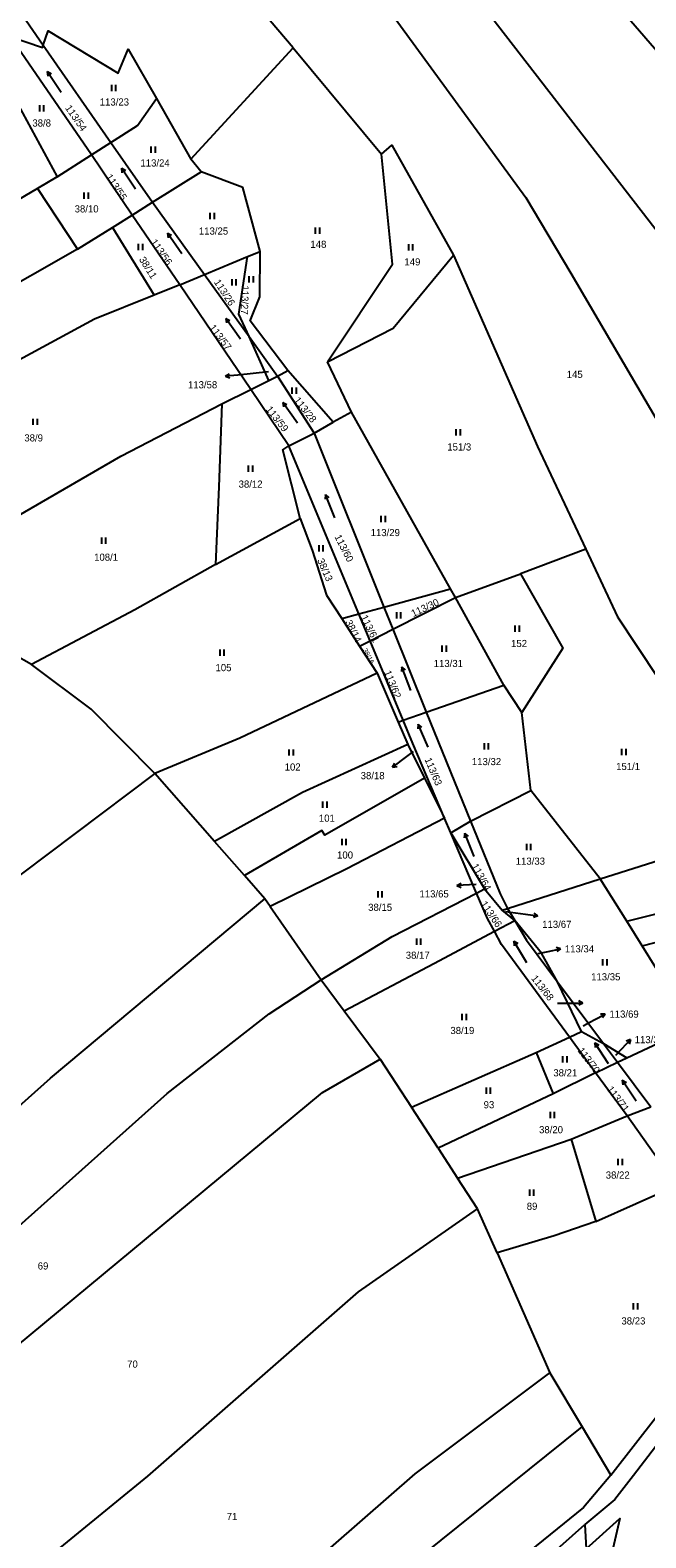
# Model space of a CAD drawing. Extents: x -7483133 to -743169, y -11317770 to -1127091.
# Drawn here: x -747508.3 to -747362, y -1131370.8 to -1131012.2 of the extents above; entities that cross this region are included whole.
import ezdxf

# ---------------------------------------------------------------- set-up
doc = ezdxf.new("R2010")
doc.units = 0
for name, color, linetype in [('Hranice parcel', 7, 'Continuous'), ('Parcelní čísla', 7, 'Continuous'), ('Pop  PČ popisy', 7, 'Continuous'), ('Značky kultur', 7, 'Continuous')]:
    doc.layers.add(name, color=color, linetype=linetype)

msp = doc.modelspace()

# ---------------------------------------------------------------- linework, layer by layer
at = {"layer": 'Hranice parcel'}
for p, q in [((-747445.77, -1131016.39), (-747480.85, -1130975.08)), ((-747511.77, -1131006.31), (-747505.21, -1131015.73)), ((-747493.76, -1131041.86), (-747513.08, -1131013.69)), ((-747505.21, -1131015.73), (-747489.11, -1131038.86)), ((-747470.12, -1131042.87), (-747445.77, -1131016.39)), ((-747445.77, -1131016.39), (-747424.82, -1131041.7)), ((-747478.31, -1131028.41), (-747470.12, -1131042.87)), ((-747493.76, -1131041.86), (-747489.11, -1131038.86)), ((-747489.11, -1131038.86), (-747479.21, -1131053.09)), ((-747501.87, -1131047.09), (-747493.76, -1131041.86)), ((-747484.08, -1131056.18), (-747493.76, -1131041.86)), ((-747467.67, -1131045.88), (-747470.12, -1131042.87)), ((-747501.87, -1131047.09), (-747506.57, -1131049.83)), ((-747479.21, -1131053.09), (-747467.67, -1131045.88)), ((-747506.57, -1131049.83), (-747497.04, -1131064.23)), ((-747484.08, -1131056.18), (-747479.21, -1131053.09)), ((-747479.21, -1131053.09), (-747466.89, -1131070.28)), ((-747497.04, -1131064.23), (-747488.78, -1131059.1)), ((-747488.78, -1131059.1), (-747484.08, -1131056.18)), ((-747488.78, -1131059.1), (-747478.83, -1131075.18)), ((-747472.77, -1131072.73), (-747484.08, -1131056.18)), ((-747466.89, -1131070.28), (-747456.65, -1131066.03)), ((-747456.65, -1131066.03), (-747453.62, -1131064.84)), ((-747472.77, -1131072.73), (-747478.83, -1131075.18)), ((-747472.77, -1131072.73), (-747466.89, -1131070.28)), ((-747455.83, -1131097.63), (-747472.77, -1131072.73)), ((-747466.89, -1131070.28), (-747456.29, -1131085.07)), ((-747456.29, -1131085.07), (-747449.55, -1131094.47)), ((-747451.56, -1131095.48), (-747456.29, -1131085.07)), ((-747431.95, -1131103.02), (-747437.65, -1131091.07)), ((-747451.56, -1131095.48), (-747449.55, -1131094.47)), ((-747449.55, -1131094.47), (-747447.06, -1131093.1)), ((-747449.55, -1131094.47), (-747440.84, -1131108.03)), ((-747436.27, -1131105.41), (-747447.06, -1131093.1)), ((-747462.74, -1131101.03), (-747455.83, -1131097.63)), ((-747455.83, -1131097.63), (-747451.56, -1131095.48)), ((-747446.81, -1131111.05), (-747455.83, -1131097.63)), ((-747440.84, -1131108.03), (-747436.27, -1131105.41)), ((-747431.95, -1131103.02), (-747436.27, -1131105.41)), ((-747408.38, -1131145.07), (-747431.95, -1131103.02)), ((-747446.81, -1131111.05), (-747440.84, -1131108.03)), ((-747440.84, -1131108.03), (-747424.22, -1131149.41)), ((-747430.18, -1131151.04), (-747446.81, -1131111.05)), ((-747464.26, -1131139.24), (-747444.14, -1131128.36)), ((-747376.22, -1131135.6), (-747391.74, -1131141.48)), ((-747407.22, -1131147.14), (-747391.74, -1131141.48)), ((-747424.22, -1131149.41), (-747408.38, -1131145.07)), ((-747407.22, -1131147.14), (-747408.38, -1131145.07)), ((-747422.11, -1131154.66), (-747407.22, -1131147.14)), ((-747395.7, -1131168), (-747407.22, -1131147.14)), ((-747434.26, -1131152.16), (-747430.18, -1131151.04)), ((-747434.26, -1131152.16), (-747430.03, -1131158.67)), ((-747430.18, -1131151.04), (-747424.22, -1131149.41)), ((-747427.53, -1131157.41), (-747430.18, -1131151.04)), ((-747424.22, -1131149.41), (-747422.11, -1131154.66)), ((-747427.53, -1131157.41), (-747422.11, -1131154.66)), ((-747422.11, -1131154.66), (-747414.16, -1131174.44)), ((-747508, -1131163.09), (-747518.15, -1131157.34)), ((-747430.03, -1131158.67), (-747427.53, -1131157.41)), ((-747430.03, -1131158.67), (-747425.84, -1131165.11)), ((-747419.66, -1131176.34), (-747427.53, -1131157.41)), ((-747425.84, -1131165.11), (-747420.83, -1131176.75)), ((-747414.16, -1131174.44), (-747395.7, -1131168)), ((-747391.42, -1131174.47), (-747395.7, -1131168)), ((-747420.83, -1131176.75), (-747419.66, -1131176.34)), ((-747420.83, -1131176.75), (-747418.53, -1131182.09)), ((-747419.66, -1131176.34), (-747414.16, -1131174.44)), ((-747414.16, -1131174.44), (-747403.63, -1131200.37)), ((-747389.33, -1131193.02), (-747391.42, -1131174.47)), ((-747418.53, -1131182.09), (-747414.55, -1131190.08)), ((-747464.5, -1131205.17), (-747478.68, -1131189)), ((-747414.55, -1131190.08), (-747409.79, -1131199.63)), ((-747403.63, -1131200.37), (-747389.33, -1131193.02)), ((-747372.79, -1131214.07), (-747389.33, -1131193.02)), ((-747408.32, -1131203.08), (-747409.79, -1131199.63)), ((-747408.32, -1131203.08), (-747403.63, -1131200.37)), ((-747372.79, -1131214.07), (-747335.3, -1131202.07)), ((-747457.41, -1131213.25), (-747464.5, -1131205.17)), ((-747402.18, -1131217.46), (-747408.32, -1131203.08)), ((-747408.32, -1131203.08), (-747400.3, -1131216.43)), ((-747452.5, -1131218.84), (-747457.41, -1131213.25)), ((-747402.18, -1131217.46), (-747400.3, -1131216.43)), ((-747400.3, -1131216.43), (-747396.13, -1131221.54)), ((-747394.81, -1131221.1), (-747372.79, -1131214.07)), ((-747366.49, -1131224.14), (-747372.79, -1131214.07)), ((-747451.24, -1131220.66), (-747452.5, -1131218.84)), ((-747451.24, -1131220.66), (-747439.12, -1131238.12)), ((-747397.95, -1131226.54), (-747393.08, -1131223.94)), ((-747396.13, -1131221.54), (-747394.81, -1131221.1)), ((-747393.08, -1131223.94), (-747396.13, -1131221.54)), ((-747394.81, -1131221.1), (-747393.08, -1131223.94)), ((-747362.83, -1131229.98), (-747366.49, -1131224.14)), ((-747359.55, -1131235.22), (-747362.83, -1131229.98)), ((-747439.12, -1131238.12), (-747433.68, -1131245.43)), ((-747377.23, -1131250.36), (-747382.92, -1131238.52)), ((-747382.92, -1131238.52), (-747372.02, -1131253.19)), ((-747433.68, -1131245.43), (-747425.11, -1131256.95)), ((-747366.48, -1131256.66), (-747350.79, -1131249.21)), ((-747388.07, -1131255.34), (-747380.11, -1131251.72)), ((-747380.11, -1131251.72), (-747377.23, -1131250.36)), ((-747373.91, -1131260.21), (-747380.11, -1131251.72)), ((-747377.23, -1131250.36), (-747372.02, -1131253.19)), ((-747417.7, -1131268.35), (-747388.07, -1131255.34)), ((-747388.07, -1131255.34), (-747384.01, -1131265.18)), ((-747372.02, -1131253.19), (-747366.48, -1131256.66)), ((-747372.02, -1131253.19), (-747368.67, -1131257.7)), ((-747368.67, -1131257.7), (-747366.48, -1131256.66)), ((-747425.11, -1131256.95), (-747417.7, -1131268.35)), ((-747373.91, -1131260.21), (-747384.01, -1131265.18)), ((-747373.91, -1131260.21), (-747368.67, -1131257.7)), ((-747366.42, -1131270.45), (-747373.91, -1131260.21)), ((-747368.67, -1131257.7), (-747360.8, -1131268.29)), ((-747384.01, -1131265.18), (-747411.33, -1131278.16)), ((-747411.33, -1131278.16), (-747417.7, -1131268.35)), ((-747379.74, -1131275.95), (-747366.42, -1131270.45)), ((-747366.42, -1131270.45), (-747360.8, -1131268.29)), ((-747354.67, -1131286.99), (-747366.42, -1131270.45)), ((-747411.33, -1131278.16), (-747406.7, -1131285.28)), ((-747406.7, -1131285.28), (-747379.74, -1131275.95)), ((-747379.74, -1131275.95), (-747373.86, -1131295.58)), ((-747401.97, -1131292.55), (-747406.7, -1131285.28)), ((-747373.86, -1131295.58), (-747354.67, -1131286.99)), ((-747397.34, -1131303.04), (-747401.97, -1131292.55)), ((-747397.34, -1131303.04), (-747384.78, -1131331.55)), ((-747370.27, -1131355.92), (-747336.38, -1131312.26)), ((-747384.78, -1131331.55), (-747377.13, -1131344.4)), ((-747377.13, -1131344.4), (-747370.27, -1131355.92))]:
    msp.add_line(p, q, dxfattribs=at)
for points in [[(-747442.73, -1130923.69), (-747390.58, -1130980.92), (-747354.26, -1131022.92), (-747339.61, -1131040.16), (-747322.4, -1131062.04), (-747305.83, -1131083.32), (-747294.44, -1131099.65), (-747274.04, -1131128.34), (-747243.06, -1131175.98)], [(-747455.08, -1130941.09), (-747407, -1130998.24), (-747346.3, -1131076.82), (-747308.86, -1131133.19), (-747276.68, -1131185.78)], [(-747466.65, -1130957.41), (-747426.05, -1131003.14), (-747390.52, -1131051.98), (-747379.77, -1131069.99), (-747357.62, -1131107.84), (-747342.16, -1131135.57), (-747326.23, -1131160.19), (-747318.42, -1131169.83), (-747304.55, -1131193.5)], [(-747505.21, -1131015.73), (-747504.08, -1131012.3), (-747487.41, -1131022.36), (-747485.06, -1131016.72), (-747478.31, -1131028.41)], [(-747513.08, -1131013.69), (-747505.41, -1131016.33), (-747505.21, -1131015.73)], [(-747521.83, -1131019.25), (-747513.23, -1131026.12), (-747501.87, -1131047.09)], [(-747489.11, -1131038.86), (-747482.82, -1131034.88), (-747478.31, -1131028.41)], [(-747424.82, -1131041.7), (-747422.32, -1131039.54), (-747407.71, -1131065.71)], [(-747437.65, -1131091.07), (-747422.19, -1131067.82), (-747424.82, -1131041.7)], [(-747453.62, -1131064.84), (-747457.76, -1131049.58), (-747467.67, -1131045.88)], [(-747506.57, -1131049.83), (-747567.11, -1131085.51), (-747578.6, -1131091.89), (-747583.1, -1131094.79)], [(-747497.04, -1131064.23), (-747519.1, -1131076.81), (-747571.91, -1131105.73)], [(-747456.29, -1131085.07), (-747458.74, -1131079.69), (-747456.65, -1131066.03)], [(-747447.06, -1131093.1), (-747456, -1131081.28), (-747453.76, -1131075.58), (-747453.62, -1131064.84)], [(-747437.65, -1131091.07), (-747422, -1131083.03), (-747407.71, -1131065.71)], [(-747407.71, -1131065.71), (-747387.68, -1131111.18), (-747376.22, -1131135.6)], [(-747478.83, -1131075.18), (-747493.05, -1131080.92), (-747560.11, -1131117.26)], [(-747534.94, -1131141.41), (-747486.76, -1131113.5), (-747462.74, -1131101.03)], [(-747462.74, -1131101.03), (-747463.44, -1131120.77), (-747464.26, -1131139.24)], [(-747444.14, -1131128.36), (-747448.25, -1131112.03), (-747446.81, -1131111.05)], [(-747444.14, -1131128.36), (-747441.29, -1131135.89), (-747437.88, -1131146.58), (-747434.26, -1131152.16)], [(-747376.22, -1131135.6), (-747368.67, -1131151.69), (-747335.3, -1131202.07)], [(-747464.26, -1131139.24), (-747483.41, -1131150.03), (-747508, -1131163.09)], [(-747391.74, -1131141.48), (-747381.7, -1131159.18), (-747391.42, -1131174.47)], [(-747366.49, -1131224.14), (-747315.64, -1131211.37), (-747239.01, -1131189.85), (-747208.02, -1131183.24), (-747142.94, -1131169.86), (-747059.23, -1131151.85), (-746994.26, -1131139.92)], [(-747362.83, -1131229.98), (-747303.37, -1131214.71), (-747236.14, -1131195.43), (-747183.65, -1131184.91), (-747140.79, -1131175.19), (-747094.5, -1131166.43), (-747035.79, -1131154.71), (-746990.07, -1131145.5)], [(-747478.68, -1131189), (-747493.84, -1131173.69), (-747508, -1131163.09)], [(-747425.84, -1131165.11), (-747458.47, -1131180.59), (-747478.68, -1131189)], [(-747409.79, -1131199.63), (-747417.35, -1131181.9), (-747419.66, -1131176.34)], [(-747418.53, -1131182.09), (-747443.59, -1131193.55), (-747464.5, -1131205.17)], [(-747478.68, -1131189), (-747516.61, -1131217.55), (-747562.75, -1131257.36), (-747584.62, -1131275.69), (-747613.72, -1131296.16)], [(-747414.55, -1131190.08), (-747438.27, -1131203.66), (-747438.96, -1131202.58), (-747457.41, -1131213.25)], [(-747409.79, -1131199.63), (-747433.07, -1131211.69), (-747451.24, -1131220.66)], [(-747403.63, -1131200.37), (-747396.62, -1131217.65), (-747394.81, -1131221.1)], [(-747587.97, -1131330.74), (-747567.99, -1131317.8), (-747522.26, -1131278.21), (-747503.48, -1131261.46), (-747452.5, -1131218.84)], [(-747439.12, -1131238.12), (-747422.3, -1131227.8), (-747402.18, -1131217.46)], [(-747397.95, -1131226.54), (-747399.59, -1131223.53), (-747402.18, -1131217.46)], [(-747393.08, -1131223.94), (-747390.29, -1131228.61), (-747382.92, -1131238.52)], [(-747382.92, -1131238.52), (-747386.77, -1131231.73), (-747393.08, -1131223.94)], [(-747433.68, -1131245.43), (-747412.33, -1131234.19), (-747397.95, -1131226.54)], [(-747380.11, -1131251.72), (-747396.26, -1131229.64), (-747397.95, -1131226.54)], [(-747573.75, -1131348.78), (-747519.29, -1131304), (-747475.75, -1131265.13), (-747451.48, -1131246.17), (-747439.12, -1131238.12)], [(-747560.74, -1131366.12), (-747532.83, -1131342.86), (-747438.82, -1131264.87), (-747425.11, -1131256.95)], [(-747534.26, -1131400.17), (-747480.38, -1131356.14), (-747430.3, -1131312.29), (-747401.97, -1131292.55)], [(-747373.86, -1131295.58), (-747383.75, -1131299), (-747397.34, -1131303.04)], [(-747333.76, -1131315.41), (-747364.89, -1131355.97), (-747369.3, -1131361.68), (-747376.46, -1131367.68)], [(-747506.23, -1131431.25), (-747474.44, -1131405.95), (-747416.83, -1131355.62), (-747384.78, -1131331.55)], [(-747495.56, -1131443.68), (-747453.65, -1131407.36), (-747419.12, -1131378.23), (-747377.13, -1131344.4)], [(-747370.27, -1131355.92), (-747376.75, -1131363.63), (-747394.3, -1131377.78), (-747413.65, -1131392.68), (-747433.29, -1131410.44), (-747454.33, -1131429.09), (-747485.81, -1131454.98)], [(-747482.98, -1131458.6), (-747465.09, -1131443.35), (-747442.92, -1131423.66), (-747415.85, -1131400.46), (-747394.73, -1131383.14), (-747385.99, -1131376.16), (-747376.46, -1131367.68)], [(-747376.46, -1131367.68), (-747376.16, -1131373.4), (-747368.11, -1131366.26), (-747372.26, -1131384.03)]]:
    msp.add_lwpolyline(points, dxfattribs=at)
at = {"layer": 'Pop  PČ popisy'}
for p, q in [((-747461.92, -1131094.51), (-747460.97, -1131093.91)), ((-747458.93, -1131094.2), (-747461.92, -1131094.51)), ((-747461.92, -1131094.51), (-747460.87, -1131094.91)), ((-747451.68, -1131093.42), (-747458.93, -1131094.2)), ((-747417.31, -1131183.76), (-747419.78, -1131185.67)), ((-747419.78, -1131185.67), (-747422.15, -1131187.52)), ((-747422.15, -1131187.52), (-747421.66, -1131186.51)), ((-747422.15, -1131187.52), (-747421.05, -1131187.3)), ((-747406.87, -1131215.61), (-747405.89, -1131215.08)), ((-747403.87, -1131215.51), (-747406.87, -1131215.61)), ((-747406.87, -1131215.61), (-747405.85, -1131216.08)), ((-747402.28, -1131215.44), (-747403.87, -1131215.51)), ((-747395.32, -1131221.83), (-747390.57, -1131222.47)), ((-747390.57, -1131222.47), (-747387.6, -1131222.89)), ((-747387.6, -1131222.89), (-747388.66, -1131223.24)), ((-747387.6, -1131222.89), (-747388.52, -1131222.25)), ((-747387.54, -1131231.81), (-747385.15, -1131231.31)), ((-747385.15, -1131231.31), (-747382.21, -1131230.69)), ((-747382.21, -1131230.69), (-747383.3, -1131230.4)), ((-747382.21, -1131230.69), (-747383.09, -1131231.38)), ((-747376.82, -1131248.99), (-747374.26, -1131247.63)), ((-747374.26, -1131247.63), (-747371.61, -1131246.22)), ((-747371.61, -1131246.22), (-747372.73, -1131246.25)), ((-747371.61, -1131246.22), (-747372.26, -1131247.13)), ((-747367.66, -1131254.49), (-747365.61, -1131252.29)), ((-747365.61, -1131252.29), (-747366.66, -1131252.69)), ((-747365.61, -1131252.29), (-747365.93, -1131253.37)), ((-747369.1, -1131256.04), (-747367.66, -1131254.49))]:
    msp.add_line(p, q, dxfattribs=at)
at = {"layer": 'Značky kultur'}
for p, q in [((-747500.93, -1131026.98), (-747504.28, -1131022)), ((-747504.28, -1131022), (-747504.15, -1131023.09)), ((-747504.28, -1131022), (-747503.32, -1131022.53)), ((-747488.94, -1131026.68), (-747488.94, -1131025.18)), ((-747487.94, -1131026.68), (-747487.94, -1131025.18)), ((-747506.04, -1131031.49), (-747506.04, -1131029.99)), ((-747505.04, -1131031.49), (-747505.04, -1131029.99)), ((-747479.54, -1131041.31), (-747479.54, -1131039.81)), ((-747478.54, -1131041.31), (-747478.54, -1131039.81)), ((-747483.3, -1131049.99), (-747486.65, -1131045.01)), ((-747486.65, -1131045.01), (-747486.52, -1131046.1)), ((-747486.65, -1131045.01), (-747485.69, -1131045.54)), ((-747495.49, -1131052.29), (-747495.49, -1131050.79)), ((-747494.49, -1131052.29), (-747494.49, -1131050.79)), ((-747465.54, -1131057.13), (-747465.54, -1131055.63)), ((-747464.54, -1131057.13), (-747464.54, -1131055.63)), ((-747440.46, -1131060.63), (-747440.46, -1131059.13)), ((-747439.46, -1131060.63), (-747439.46, -1131059.13)), ((-747482.54, -1131064.49), (-747482.54, -1131062.99)), ((-747481.54, -1131064.49), (-747481.54, -1131062.99)), ((-747472.25, -1131065.37), (-747475.69, -1131060.45)), ((-747475.69, -1131060.45), (-747475.54, -1131061.54)), ((-747475.69, -1131060.45), (-747474.72, -1131060.97)), ((-747418.34, -1131064.58), (-747418.34, -1131063.08)), ((-747417.34, -1131064.58), (-747417.34, -1131063.08)), ((-747460.34, -1131072.91), (-747460.34, -1131071.41)), ((-747459.34, -1131072.91), (-747459.34, -1131071.41)), ((-747456.23, -1131072.2), (-747456.23, -1131070.7)), ((-747455.23, -1131072.2), (-747455.23, -1131070.7)), ((-747458.35, -1131085.65), (-747461.79, -1131080.73)), ((-747461.79, -1131080.73), (-747461.64, -1131081.82)), ((-747461.79, -1131080.73), (-747460.82, -1131081.25)), ((-747446.04, -1131098.65), (-747446.04, -1131097.15)), ((-747445.04, -1131098.65), (-747445.04, -1131097.15)), ((-747444.81, -1131105.63), (-747448.25, -1131100.71)), ((-747448.25, -1131100.71), (-747448.1, -1131101.8)), ((-747448.25, -1131100.71), (-747447.28, -1131101.23)), ((-747507.6, -1131106.09), (-747507.6, -1131104.59)), ((-747506.6, -1131106.09), (-747506.6, -1131104.59)), ((-747407.04, -1131108.61), (-747407.04, -1131107.11)), ((-747406.04, -1131108.61), (-747406.04, -1131107.11)), ((-747456.41, -1131117.21), (-747456.41, -1131115.71)), ((-747455.41, -1131117.21), (-747455.41, -1131115.71)), ((-747438.13, -1131122.64), (-747438.23, -1131123.73)), ((-747435.89, -1131128.2), (-747438.13, -1131122.64)), ((-747438.13, -1131122.64), (-747437.3, -1131123.36)), ((-747424.88, -1131129.23), (-747424.88, -1131127.73)), ((-747423.88, -1131129.23), (-747423.88, -1131127.73)), ((-747491.32, -1131134.35), (-747491.32, -1131132.85)), ((-747490.32, -1131134.35), (-747490.32, -1131132.85)), ((-747439.63, -1131136.2), (-747439.63, -1131134.7)), ((-747438.63, -1131136.2), (-747438.63, -1131134.7)), ((-747421.19, -1131152.09), (-747421.19, -1131150.59)), ((-747420.19, -1131152.09), (-747420.19, -1131150.59)), ((-747393.01, -1131155.26), (-747393.01, -1131153.76)), ((-747392.01, -1131155.26), (-747392.01, -1131153.76)), ((-747463.19, -1131160.99), (-747463.19, -1131159.49)), ((-747462.19, -1131160.99), (-747462.19, -1131159.49)), ((-747410.37, -1131160.06), (-747410.37, -1131158.56)), ((-747409.37, -1131160.06), (-747409.37, -1131158.56)), ((-747419.95, -1131163.62), (-747420.07, -1131164.71)), ((-747417.8, -1131169.22), (-747419.95, -1131163.62)), ((-747419.95, -1131163.62), (-747419.14, -1131164.35)), ((-747416.12, -1131177.27), (-747416.18, -1131178.37)), ((-747413.68, -1131182.75), (-747416.12, -1131177.27)), ((-747416.12, -1131177.27), (-747415.26, -1131177.96)), ((-747446.72, -1131184.75), (-747446.72, -1131183.25)), ((-747445.72, -1131184.75), (-747445.72, -1131183.25)), ((-747400.35, -1131183.28), (-747400.35, -1131181.78)), ((-747399.35, -1131183.28), (-747399.35, -1131181.78)), ((-747367.65, -1131184.63), (-747367.65, -1131183.13)), ((-747366.65, -1131184.63), (-747366.65, -1131183.13)), ((-747438.74, -1131197.17), (-747438.74, -1131195.67)), ((-747437.74, -1131197.17), (-747437.74, -1131195.67)), ((-747434.17, -1131206.06), (-747434.17, -1131204.56)), ((-747433.17, -1131206.06), (-747433.17, -1131204.56)), ((-747405.02, -1131203.2), (-747405.12, -1131204.29)), ((-747402.78, -1131208.76), (-747405.02, -1131203.2)), ((-747405.02, -1131203.2), (-747404.19, -1131203.92)), ((-747390.28, -1131207.21), (-747390.28, -1131205.71)), ((-747389.28, -1131207.21), (-747389.28, -1131205.71)), ((-747425.63, -1131218.5), (-747425.63, -1131217)), ((-747424.63, -1131218.5), (-747424.63, -1131217)), ((-747416.42, -1131229.77), (-747416.42, -1131228.27)), ((-747415.42, -1131229.77), (-747415.42, -1131228.27)), ((-747390.27, -1131234), (-747393.36, -1131228.86)), ((-747393.36, -1131228.86), (-747393.28, -1131229.96)), ((-747393.36, -1131228.86), (-747392.42, -1131229.44)), ((-747372.15, -1131234.66), (-747372.15, -1131233.16)), ((-747371.15, -1131234.66), (-747371.15, -1131233.16)), ((-747382.94, -1131243.61), (-747376.94, -1131243.61)), ((-747376.94, -1131243.61), (-747377.92, -1131243.11)), ((-747376.94, -1131243.61), (-747377.92, -1131244.11)), ((-747405.62, -1131247.67), (-747405.62, -1131246.17)), ((-747404.62, -1131247.67), (-747404.62, -1131246.17)), ((-747370.84, -1131258.1), (-747374.11, -1131253.06)), ((-747374.11, -1131253.06), (-747373.99, -1131254.16)), ((-747374.11, -1131253.06), (-747373.15, -1131253.61)), ((-747381.66, -1131257.75), (-747381.66, -1131256.25)), ((-747380.66, -1131257.75), (-747380.66, -1131256.25)), ((-747399.86, -1131265.2), (-747399.86, -1131263.7)), ((-747398.86, -1131265.2), (-747398.86, -1131263.7)), ((-747364.28, -1131266.98), (-747367.55, -1131261.95)), ((-747367.55, -1131261.95), (-747367.43, -1131263.04)), ((-747367.55, -1131261.95), (-747366.59, -1131262.49)), ((-747384.65, -1131271.02), (-747384.65, -1131269.52)), ((-747383.65, -1131271.02), (-747383.65, -1131269.52)), ((-747368.52, -1131282.18), (-747368.52, -1131280.68)), ((-747367.52, -1131282.18), (-747367.52, -1131280.68)), ((-747389.55, -1131289.49), (-747389.55, -1131287.99)), ((-747388.55, -1131289.49), (-747388.55, -1131287.99)), ((-747364.9, -1131316.52), (-747364.9, -1131315.02)), ((-747363.9, -1131316.52), (-747363.9, -1131315.02))]:
    msp.add_line(p, q, dxfattribs=at)

# ---------------------------------------------------------------- texts
at = {"layer": 'Parcelní čísla'}
for s, height, rotation, p in [('113/54', 1.7, 305, (-747500.1, -1131030.7)), ('113/55', 1.7, 304, (-747490.46, -1131047.1)), ('113/56', 1.7, 305, (-747479.79, -1131062.6)), ('38/11', 1.7, 302, (-747482.52, -1131066.7)), ('113/26', 1.7, 303, (-747464.71, -1131072.12)), ('113/27', 1.7, 268, (-747458.02, -1131072.87)), ('113/57', 1.7, 307, (-747465.84, -1131082.95)), ('113/59', 1.7, 308, (-747452.4, -1131102.42)), ('113/28', 1.7, 308, (-747445.72, -1131100.24)), ('113/60', 1.7, 297, (-747436.02, -1131132.68)), ('38/13', 1.7, 294, (-747440.15, -1131138.28)), ('113/30', 1.7, 25, (-747417.25, -1131151.8)), ('38/14', 1.7, 297, (-747433.5, -1131152.97)), ('113/61', 1.7, 296, (-747429.79, -1131151.77)), ('38/16', 1.14, 298, (-747429.27, -1131159.6)), ('113/62', 1.7, 292, (-747424.23, -1131164.87)), ('113/63', 1.7, 293, (-747414.6, -1131185.65)), ('113/64', 1.7, 299, (-747403.45, -1131210.99)), ('113/66', 1.7, 304, (-747401.33, -1131220.04)), ('113/68', 1.7, 308, (-747389.31, -1131237.77)), ('113/70', 1.7, 307, (-747378.26, -1131254.96)), ('113/71', 1.7, 307, (-747371.32, -1131264.14))]:
    msp.add_text(s, height=height, rotation=rotation, dxfattribs=at).set_placement(p)
for s, p in [('113/23', (-747491.78, -1131030.1)), ('38/8', (-747507.8, -1131035.1)), ('113/24', (-747482.11, -1131044.61)), ('38/10', (-747497.75, -1131055.53)), ('113/25', (-747468.21, -1131060.8)), ('148', (-747441.7, -1131063.95)), ('149', (-747419.35, -1131068.13)), ('145', (-747380.76, -1131094.9)), ('113/58', (-747470.81, -1131097.37)), ('38/9', (-747509.71, -1131110.01)), ('151/3', (-747409.16, -1131112.16)), ('38/12', (-747458.77, -1131121)), ('113/29', (-747427.38, -1131132.53)), ('108/1', (-747493.12, -1131138.39)), ('152', (-747394, -1131158.92)), ('105', (-747464.26, -1131164.66)), ('113/31', (-747412.39, -1131163.67)), ('102', (-747447.82, -1131188.3)), ('113/32', (-747403.31, -1131187.01)), ('151/1', (-747369.02, -1131188.17)), ('38/18', (-747429.75, -1131190.35)), ('101', (-747439.68, -1131200.47)), ('100', (-747435.36, -1131209.24)), ('113/33', (-747392.89, -1131210.7)), ('113/65', (-747415.77, -1131218.48)), ('38/15', (-747427.97, -1131221.68)), ('113/67', (-747386.6, -1131225.72)), ('38/17', (-747419.03, -1131233.07)), ('113/34', (-747381.21, -1131231.55)), ('113/35', (-747374.96, -1131238.21)), ('113/69', (-747370.61, -1131247.08)), ('38/19', (-747408.42, -1131250.98)), ('113/36', (-747364.61, -1131253.15)), ('38/21', (-747383.95, -1131261.05)), ('93', (-747400.52, -1131268.64)), ('38/20', (-747387.34, -1131274.58)), ('38/22', (-747371.49, -1131285.37)), ('89', (-747390.27, -1131292.8)), ('69', (-747506.53, -1131307)), ('38/23', (-747367.76, -1131320.07)), ('70', (-747485.27, -1131330.34)), ('71', (-747461.6, -1131366.6))]:
    msp.add_text(s, height=1.7, dxfattribs=at).set_placement(p)

doc.saveas('drawing.dxf')
